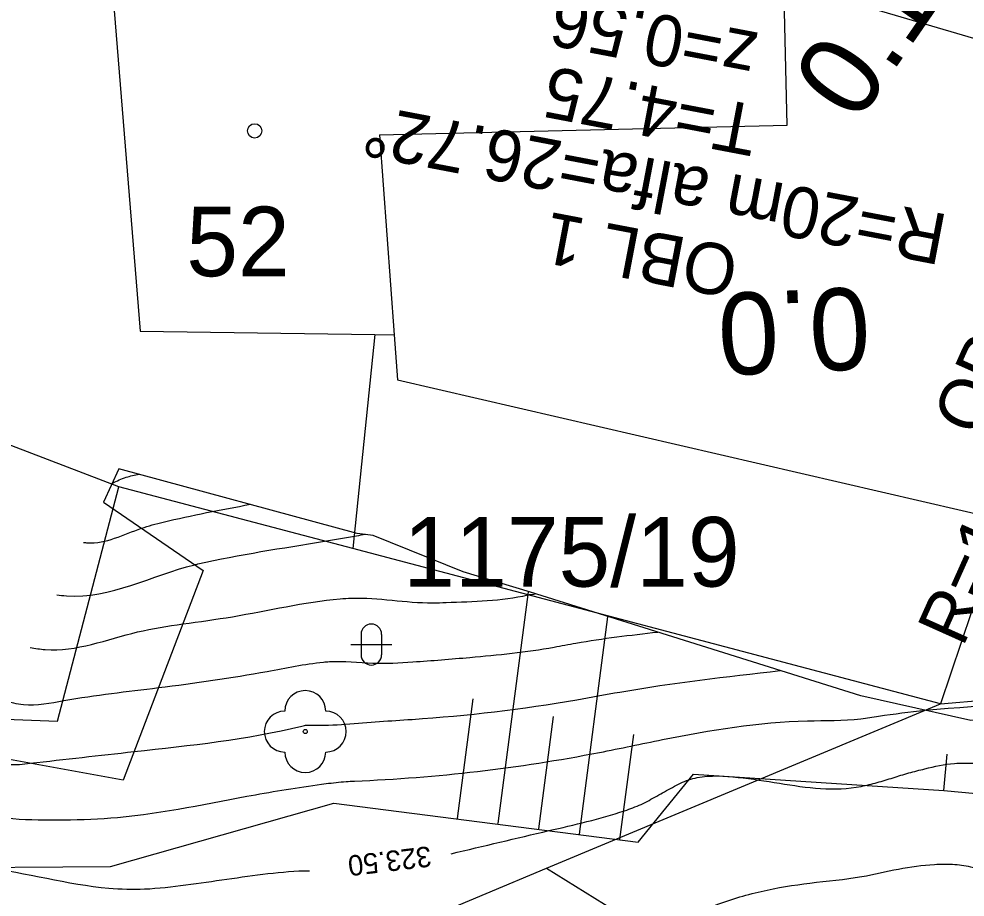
# Model space of a CAD drawing. Extents: x -564091 to -563943, y -1163604 to -1163394.
# Drawn here: x -564041.34 to -564018.23, y -1163497.39 to -1163475.95 of the extents above; entities that cross this region are included whole.
import ezdxf

# ---------------------------------------------------------------- set-up
doc = ezdxf.new("R2010")
doc.units = 0
for name, color, linetype in [('_popis staničení PRI1', 7, 'Continuous'), ('Hranice parcel', 7, 'Continuous'), ('Parcelní čísla', 7, 'Continuous'), ('Vnitřní kresba', 7, 'Continuous'), ('Vrstva 14', 7, 'Continuous'), ('Vrstva 22', 7, 'Continuous'), ('Vrstva 24', 7, 'Continuous'), ('Vrstva 25', 7, 'Continuous'), ('Vrstva 26', 7, 'Continuous'), ('Vrstva 48', 7, 'Continuous'), ('Značky budov', 7, 'Continuous')]:
    doc.layers.add(name, color=color, linetype=linetype)

msp = doc.modelspace()

# ---------------------------------------------------------------- linework, layer by layer
at = {"layer": 'Hranice parcel'}
for p, q in [((-564032.65, -1163483.65), (-564033.19, -1163488.88)), ((-564033.19, -1163488.88), (-564038.9, -1163487.37)), ((-564018.83, -1163492.67), (-564033.19, -1163488.88)), ((-564018.83, -1163492.67), (-564003.59, -1163491.36)), ((-564028.46, -1163496.69), (-564018.83, -1163492.67)), ((-564034.52, -1163499.22), (-564028.46, -1163496.69))]:
    msp.add_line(p, q, dxfattribs=at)
for points in [[(-564039.04, -1163475.43), (-564029.42, -1163475.59), (-564022.66, -1163475.05), (-564001.49, -1163481.27)], [(-564039.04, -1163475.43), (-564038.38, -1163483.57), (-564032.65, -1163483.65)], [(-564038.9, -1163487.37), (-564054.87, -1163481.26), (-564054.55, -1163476.46), (-564062.08, -1163477.1), (-564062.07, -1163477.63)], [(-564032.65, -1163483.65), (-564032.18, -1163483.66), (-564032.1, -1163484.76), (-564017.32, -1163488.18), (-564018.83, -1163492.67)], [(-564061.85, -1163489.87), (-564050.33, -1163492.71), (-564040.4, -1163493.1), (-564038.9, -1163487.37)], [(-564028.46, -1163496.69), (-564025.15, -1163498.74), (-564020.95, -1163501.38), (-564021.23, -1163504.52), (-564021.9, -1163513.74)]]:
    msp.add_lwpolyline(points, dxfattribs=at)
at = {"layer": 'Vnitřní kresba'}
for p, q in [((-564022.58, -1163478.54), (-564022.66, -1163475.05)), ((-564032.54, -1163478.78), (-564022.58, -1163478.54)), ((-564032.54, -1163478.78), (-564032.18, -1163483.66))]:
    msp.add_line(p, q, dxfattribs=at)
at = {"layer": 'Vrstva 14'}
for points in [[(-564033.08, -1163488.51), (-564038.9, -1163486.93), (-564039.28, -1163487.75)], [(-564039.28, -1163487.75), (-564036.84, -1163489.42), (-564038.8, -1163494.54), (-564041.75, -1163494)], [(-564032.69, -1163488.56), (-564033.08, -1163488.51)], [(-564005.7, -1163491.6), (-564006.2, -1163491.58), (-564012.27, -1163492.36), (-564018.09, -1163493.08), (-564020.78, -1163492.48), (-564028.85, -1163489.95), (-564030.49, -1163489.45), (-564032.69, -1163488.56)], [(-564043.78, -1163496.68), (-564039.11, -1163496.65), (-564033.65, -1163495.1), (-564026.22, -1163496.05), (-564024.87, -1163494.39), (-564018.75, -1163494.79), (-564015.5, -1163495.09), (-564011.97, -1163494.31)]]:
    msp.add_lwpolyline(points, dxfattribs=at)
at = {"layer": 'Vrstva 22'}
msp.add_circle((-564034.35, -1163493.35), 0.05, dxfattribs=at)
for centre, start, end in [((-564034.35, -1163492.85), 0, 180), ((-564034.85, -1163493.35), 90, 270), ((-564033.85, -1163493.35), 270, 90), ((-564034.35, -1163493.85), 180, 0)]:
    msp.add_arc(centre, 0.5, start, end, dxfattribs=at)
at = {"layer": 'Vrstva 24'}
for points in [[(-564040.42, -1163490.01), (-564040.184, -1163490.036), (-564037.051, -1163489.276), (-564036.974, -1163489.258), (-564033.879, -1163488.703), (-564033.095, -1163488.569), (-564032.88, -1163488.53)], [(-564041.72, -1163492.59), (-564041.232, -1163492.69), (-564040.244, -1163492.595), (-564037.934, -1163492.277), (-564035.281, -1163491.88), (-564033.905, -1163491.655), (-564033.758, -1163491.643), (-564032.696, -1163491.679), (-564031.72, -1163491.649), (-564030.331, -1163491.539), (-564028.273, -1163491.289), (-564027.738, -1163491.19), (-564025.74, -1163490.92)], [(-564043.01, -1163495.16), (-564042.704, -1163495.259), (-564040.249, -1163495.507), (-564038.933, -1163495.447), (-564035.565, -1163494.892), (-564033.841, -1163494.623), (-564033.354, -1163494.57), (-564033.147, -1163494.56), (-564027.164, -1163493.861), (-564025.624, -1163493.548), (-564022.084, -1163493.089), (-564020.777, -1163493.039), (-564020.345, -1163492.975), (-564019.205, -1163492.831), (-564014.698, -1163492.66), (-564013.156, -1163492.656), (-564012.231, -1163492.615), (-564007.86, -1163491.79)], [(-564031.812, -1163499.5), (-564030.324, -1163499.377), (-564029.547, -1163499.242), (-564028.773, -1163499.061), (-564028.001, -1163498.908), (-564027.615, -1163498.867), (-564027.23, -1163498.862), (-564026.607, -1163498.989), (-564026.346, -1163499.024), (-564026.173, -1163498.931), (-564026.053, -1163498.733), (-564025.945, -1163498.506), (-564025.804, -1163498.324), (-564025.519, -1163498.129), (-564024.955, -1163497.86), (-564024.387, -1163497.614), (-564023.213, -1163497.254), (-564022.022, -1163497.051), (-564020.757, -1163496.892), (-564019.862, -1163496.708), (-564018.98, -1163496.594), (-564018.537, -1163496.592), (-564018.102, -1163496.651), (-564017.139, -1163496.933), (-564016.188, -1163497.257), (-564015.239, -1163497.589), (-564014.283, -1163497.894), (-564013.587, -1163498.092), (-564013.3, -1163498.155), (-564013.009, -1163498.205), (-564012.719, -1163498.253), (-564012.43, -1163498.312), (-564010.133, -1163499.025), (-564009.7, -1163499.224), (-564009.288, -1163499.466), (-564008.873, -1163499.71), (-564008.431, -1163499.916), (-564006.88, -1163500.213), (-564005.699, -1163500.108), (-564005.367, -1163500.004), (-564005.352, -1163499.957), (-564005.385, -1163499.904), (-564005.432, -1163499.847), (-564005.458, -1163499.79), (-564005.454, -1163499.732), (-564005.373, -1163499.663), (-564004.291, -1163498.6), (-564003.237, -1163497.506), (-564002.153, -1163496.417), (-564001.583, -1163495.886), (-564000.985, -1163495.371), (-564000.543, -1163495.196), (-564000.072, -1163495.171), (-563999.593, -1163495.223), (-563999.117, -1163495.267), (-563998.655, -1163495.218), (-563997.978, -1163494.98), (-563997.317, -1163494.68), (-563996.656, -1163494.38), (-563995.98, -1163494.14), (-563995.697, -1163494.069), (-563995.41, -1163494.016), (-563995.123, -1163493.963), (-563994.84, -1163493.89), (-563994.137, -1163493.61)]]:
    msp.add_spline(points, degree=3, dxfattribs=at)
at = {"layer": 'Vrstva 25'}
for p, q in [((-564032.986, -1163490.976), (-564032.986, -1163491.476)), ((-564032.486, -1163490.976), (-564032.486, -1163491.476)), ((-564033.236, -1163491.226), (-564032.236, -1163491.226))]:
    msp.add_line(p, q, dxfattribs=at)
for centre, start, end in [((-564032.736, -1163490.976), 0, 180), ((-564032.736, -1163491.476), 180, 0)]:
    msp.add_arc(centre, 0.25, start, end, dxfattribs=at)
msp.add_spline([(-564039.06, -1163487.28), (-564038.725, -1163487.141), (-564038.41, -1163487.06)], degree=3, dxfattribs=at)
at = {"layer": 'Vrstva 26'}
for points in [[(-564039.77, -1163488.73), (-564039.671, -1163488.74), (-564038.352, -1163488.385), (-564037.82, -1163488.236), (-564035.69, -1163487.8)], [(-564030.787, -1163496.336), (-564028.401, -1163495.771), (-564026.55, -1163495.284), (-564026.147, -1163495.128), (-564025.763, -1163494.926), (-564025.381, -1163494.714), (-564024.983, -1163494.529), (-564024.778, -1163494.476), (-564023.777, -1163494.469), (-564022.768, -1163494.613), (-564021.761, -1163494.742), (-564020.768, -1163494.69), (-564020.378, -1163494.594), (-564019.992, -1163494.479), (-564019.605, -1163494.362), (-564019.215, -1163494.261), (-564018.494, -1163494.127), (-564018.03, -1163494.125), (-564017.565, -1163494.144), (-564016.635, -1163494.209), (-564015.486, -1163494.302), (-564014.546, -1163494.457), (-564013.618, -1163494.674), (-564013.287, -1163494.768), (-564012.961, -1163494.879), (-564012.635, -1163494.991), (-564012.302, -1163495.087), (-564011.185, -1163495.184), (-564010.325, -1163495.07), (-564009.466, -1163494.913), (-564008.615, -1163494.71), (-564007.775, -1163494.461), (-564005.875, -1163493.819), (-564004.998, -1163493.505), (-564003.872, -1163493.237), (-564002.608, -1163493.074), (-563997.404, -1163492.441), (-563996.84, -1163492.35), (-563996.277, -1163492.238), (-563995.433, -1163492.101), (-563995.293, -1163492.088), (-563995.152, -1163492.08), (-563994.744, -1163492.153), (-563994.067, -1163492.223), (-563993.74, -1163492.055), (-563993.078, -1163491.408), (-563992.901, -1163491.103), (-563992.782, -1163490.74), (-563992.679, -1163490.374), (-563992.526, -1163489.633), (-563992.48, -1163489.295), (-563992.41, -1163488.908)], [(-564041.07, -1163491.3), (-564040.702, -1163491.348), (-564038.446, -1163490.918), (-564037.338, -1163490.722), (-564036.127, -1163490.545), (-564033.5, -1163490.11), (-564033.221, -1163490.093), (-564031.239, -1163490.207), (-564030.908, -1163490.198), (-564028.91, -1163490.014), (-564028.829, -1163490), (-564028.806, -1163489.999), (-564028.73, -1163489.99)], [(-564042.37, -1163493.87), (-564041.834, -1163494.111), (-564041.598, -1163494.152), (-564041.067, -1163494.125), (-564038.532, -1163493.84), (-564034.433, -1163493.218), (-564034.309, -1163493.194), (-564034.195, -1163493.193), (-564032.535, -1163493.106), (-564031.742, -1163493.053), (-564027.719, -1163492.573), (-564026.667, -1163492.385), (-564022.75, -1163491.86)], [(-564043.66, -1163496.45), (-564043.616, -1163496.463), (-564042.182, -1163496.67), (-564039.148, -1163497.174), (-564038.274, -1163497.194), (-564037.269, -1163497.097), (-564036.266, -1163496.955), (-564035.262, -1163496.821), (-564034.254, -1163496.749), (-564034.245, -1163496.749)]]:
    msp.add_spline(points, degree=3, dxfattribs=at)
at = {"layer": 'Vrstva 48'}
for p, q in [((-564029.638, -1163495.6), (-564028.895, -1163489.936)), ((-564027.655, -1163495.86), (-564026.958, -1163490.546)), ((-564030.63, -1163495.47), (-564030.247, -1163492.55)), ((-564028.647, -1163495.73), (-564028.287, -1163492.986)), ((-564026.664, -1163495.99), (-564026.327, -1163493.421)), ((-564018.75, -1163494.79), (-564018.668, -1163493.902))]:
    msp.add_line(p, q, dxfattribs=at)
at = {"layer": 'Značky budov'}
msp.add_circle((-564035.587, -1163478.679), 0.175, dxfattribs=at)

# ---------------------------------------------------------------- texts
at = {"layer": '_popis staničení PRI1'}
for s, height, rotation, p in [('R=8m alfa=84.12%%d', 1.25, 118.4715, (-564013.646, -1163477.526)), ('0.1', 2, 55.3596, (-564020.883, -1163478.531)), ('   z=0.56', 1.25, 169.2083, (-564021.866, -1163476.552)), ('  T=4.75', 1.25, 169.2083, (-564022.306, -1163478.25)), ('R=10m alfa=21.05%%d', 1.25, 65.8848, (-564018.289, -1163491.313)), ('R=20m alfa=26.72%%d', 1.25, 169.2083, (-564018.613, -1163480.735)), ('OBL 1', 1.25, 169.2083, (-564023.711, -1163481.545)), ('OBL 4', 1.25, 65.8848, (-564017.914, -1163486.193)), ('0.0', 2, 182.5694, (-564020.599, -1163482.491))]:
    msp.add_text(s, height=height, rotation=rotation, dxfattribs=at).set_placement(p)
at = {"layer": 'Parcelní čísla'}
for s, p in [('52', (-564037.256, -1163482.23)), ('1175/19', (-564031.956, -1163489.81))]:
    msp.add_text(s, height=1.7, dxfattribs=at).set_placement(p)
at = {"layer": 'Vrstva 25'}
msp.add_text('323.50', height=0.5, rotation=186.8068, dxfattribs=at).set_placement((-564031.301, -1163496.146))

doc.saveas('drawing.dxf')
